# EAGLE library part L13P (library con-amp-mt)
AMP MT CONNECTOR
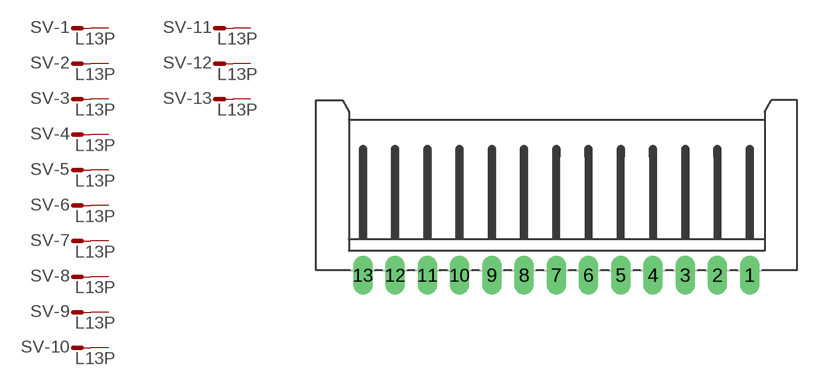
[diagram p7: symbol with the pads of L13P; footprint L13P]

Designator prefix SV; gates -1=M -2=M -3=M -4=M -5=M -6=M -7=M -8=M -9=M -10=M -11=M -12=M -13=M

## L13P (OC_FARNELL: unknown; OC_NEWARK: unknown)  [L13P]
1  -1:S  pas
2  -2:S  pas
3  -3:S  pas
4  -4:S  pas
5  -5:S  pas
6  -6:S  pas
7  -7:S  pas
8  -8:S  pas
9  -9:S  pas
10  -10:S  pas
11  -11:S  pas
12  -12:S  pas
13  -13:S  pas

## Footprint L13P (pad centres in mm)
AMP MT CONNECTOR
drill 1.016 long: 1 15,-6.25; 2 12.5,-6.25; 3 10,-6.25; 4 7.5,-6.25; 5 5,-6.25; 6 2.5,-6.25; 7 0,-6.25; 8 -2.5,-6.25; 9 -5,-6.25; 10 -7.5,-6.25; 11 -10,-6.25; 12 -12.5,-6.25; 13 -15,-6.25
